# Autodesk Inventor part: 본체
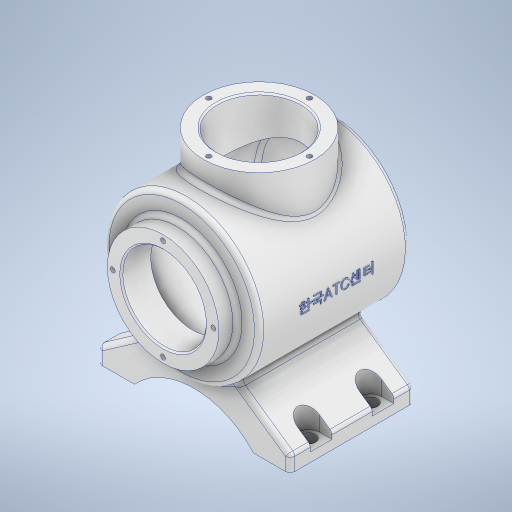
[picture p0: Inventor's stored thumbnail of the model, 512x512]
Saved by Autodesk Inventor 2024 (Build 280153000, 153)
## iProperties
Created: 2023-08
Part Number: 본체
Material: 알루미늄 6061
Document SubType Name: Modeling
Designer: Owner
Density: 2.7 g/cm^3
Appearance: 알루미늄 - 평지
Mass: 1296.69 g
Surface Area: 1060.44 cm^2
Volume: 480.256 cm^3
Author: Owner
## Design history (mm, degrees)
sketch "스케치1"
  geometry: L1 (0, 0)-(0, -120); L2 (36, 0)-(36, -12); L3 (36, -12)-(50, -12); L4 (50, -12)-(50, -108.336); L5 (27, -19)-(43, -19); L6 (43, -19)-(43, -103.887); L7 (27, -19)-(27, 0); L8 (27, 0)-(36, 0); A1 r 113 centre (0, -7) between (0, -120) and (50, -108.336); A2 r 106 centre (0, -7) between (0, -113) and (43, -103.887)
  constraints: 16 end point, 4 point on circle, 4 vertical, 2 centre point, 2 perpendicular, 2 point on line, 1 horizontal alignment, 2 other
  dimensions: "d0" = 120 distance of L1.start L1.end; "d1" = 113 radius of A1; "d2" = 72 diameter of L2 L1; "d3" = 100 diameter of L4 L1; "d4" = 108 distance from line of L1.end L3; "d5" = 7 radial gap between concentric circles of A1 A2; "d6" = 54 diameter of L7 L1
revolve "회전1" sketch "스케치1" stored, may be unused: angle "d7" = 90 deg
fillet "모깎기1" dims "d8" = 3
node "작업 평면1"
sketch "스케치2"
  geometry: C1 r 36 at (0, -62); 1 further point
  constraints: 1 centre point, 1 vertical alignment
  dimensions: "d10" = 72 diameter of C1; "d11" = 62 distance of point (0, 0) C1.centre
extrude "돌출1" join sketch "스케치2" stored distance "d12" = 10; taper "d13" = 0 deg
sketch "스케치3"
  geometry: C1 r 36 at (0, 0) reference; 2 further points
  constraints: 1 coincident
hole "구멍1" sketch "스케치3" at (0, 0) diameter "d14" = 54; stored, may be unused: countersink angle "d18" = 90 deg, drill point angle "d20" = 118 deg; dims "d15" = 8, "d16" = 4, "d17" = 2, "d19" = 48
sketch "스케치4"
  geometry: C1 r 27 at (0, 0) reference; 2 further points
  constraints: 1 vertical alignment
  dimensions: "d21" = 32.5 distance of C1.centre point (0, 32.5)
hole "구멍2" sketch "스케치4" at (0, 32.5) diameter "d22" = 3.242; stored, may be unused: countersink angle "d26" = 90 deg, drill point angle "d28" = 118 deg; dims "d23" = 8, "d24" = 4, "d25" = 2, "d27" = 10
sketch "스케치5"
  geometry: 2 further points
  constraints: 1 vertical alignment
  dimensions: "d32" = 32.5 distance of point (0, 0) point (0, 32.5)
hole "구멍3" sketch "스케치5" at (0, 32.5) diameter "d33" = 3.242; stored, may be unused: countersink angle "d37" = 90 deg, drill point angle "d39" = 118 deg; dims "d34" = 8, "d35" = 4, "d36" = 2, "d38" = 10
fillet "모깎기2" dims "d43" = 3
node "작업 평면2"
sketch "스케치6"
  geometry: L1 (-62, -67)-(-62, -77); L2 (-62, -77)-(-38.5, -77); L3 (26.694, -42.278)-(62, -67); L4 (62, -67)-(62, -77); L5 (62, -77)-(38.5, -77); L6 (-62, -67)-(-26.694, -42.278); A1 r 50 centre (0, 0) between (26.694, -42.278) and (-26.694, -42.278) reference; A2 r 52.096 centre (0, -112.096) between (38.5, -77) and (-38.5, -77); 2 further points
  constraints: 12 end point, 5 point on circle, 3 equal length, 2 perpendicular, 2 vertical, 2 vertical alignment, 1 centre point
  dimensions: "d45" = 17 distance from line of L5 point (0, -60); "d47" = 55 deg angle of L4 L3; "d48" = 10 distance of L4.end L3.end; "d49" = 77 distance of L2.end L5.end; "d50" = 124 distance of L4.end L1.end; "d51" = 77 distance from line of L5 point (0, 0)
extrude "돌출2" join sketch "스케치6" stored distance "d52" = 80; taper "d53" = 0 deg
node "작업 평면3"
sketch "스케치7"
  geometry: L1 (-54, -80)-(-79.632, -80); L2 (-54, -73)-(-62, -73); L3 (-62, -87)-(-54, -87); L4 (-62, -100)-(-38.5, -100) reference; L5 (-62, -100)-(-62, -20) reference; L6 (54, -80)-(75.93, -80); L7 (54, -73)-(62, -73); L8 (62, -87)-(54, -87); L9 (62, -20)-(62, -100) reference; A1 r 7 centre (-54, -80) between (-54, -87) and (-54, -73); A2 r 7 centre (54, -80) between (54, -73) and (54, -87); 3 further points
  constraints: 16 end point, 4 horizontal, 4 point on circle, 4 point on line, 4 tangent, 2 centre point, 2 midpoint, 2 parallel, 1 horizontal alignment
  dimensions: "d55" = 20 distance between parallel lines of L4 L1; "d56" = 14 distance between parallel lines of L3 L2; "d57" = 8 distance from line of L5 L1.start; "d58" = 14 distance between parallel lines of L8 L7; "d59" = 8 distance from line of L9 L6.start
extrude "돌출3" cut sketch "스케치7" distance "d60" = 21.5; taper "d61" = 0 deg
sketch "스케치8"
  geometry: A1 r 7 centre (54, 80) between (54, 87) and (54, 73) reference; 2 further points
  constraints: 1 coincident
hole "구멍4" sketch "스케치8" at (54, 80) diameter "d62" = 9; stored, may be unused: countersink angle "d66" = 90 deg, drill point angle "d68" = 118 deg; dims "d63" = 8, "d64" = 4, "d65" = 2, "d67" = 10
fillet "모깎기3" dims "d72" = 3
fillet "모깎기4" dims "d73" = 3
fillet "모깎기5" dims "d74" = 3
chamfer "모따기1" distance "d75" = 1; stored, may be unused: second distance "d76" = 2, angle "d77" = 45 deg
node "작업 평면4"
sketch "스케치9"
  geometry: L1 (-36, 60.168)-(36, 60.168) reference; 3 further points
  constraints: 1 midpoint, 1 vertical alignment, 1 other
  dimensions: "d78" = 62 distance from line of L1 point (0, -1.832)
feature "엠보싱1" sketch "스케치9" dims "d0" = 120, "d1" = 113, "d2" = 72, "d3" = 100, "d4" = 108, "d5" = 7, "d6" = 54, "d79" = 0.5, "d80" = 0
node "솔리드1"
pattern_circular "원형 패턴1" dims angle "d30" = 360 deg
pattern_circular "원형 패턴2" dims angle "d41" = 360 deg
mirror "미러1"
pattern_linear "직사각형 패턴1" dims "d71" = 40
feature "A9D066F2-1C7D-4E18-AEED-F7BC21143FA4" dims "d14" = 54, "d15" = 8, "d16" = 4, "d17" = 2, "d18" = 90 deg, "d19" = 48, "d20" = 118 deg
other parameters: "d9" = 65, "d54" = -71
